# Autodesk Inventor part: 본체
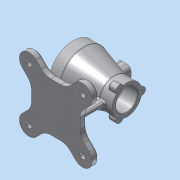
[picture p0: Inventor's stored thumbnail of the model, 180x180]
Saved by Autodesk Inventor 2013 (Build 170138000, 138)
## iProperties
Created: 2018-03
Part Number: 본체
Material: 알루미늄 6061
Document SubType Name: Modeling
Designer: Administrator
Density: 2.71 g/cm^3
Mass: 1014.37 g
Surface Area: 854.98 cm^2
Volume: 374.307 cm^3
Author: Administrator
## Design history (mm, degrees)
sketch "스케치1"
  geometry: L1 (-50, 0)-(-50, 45); L2 (50, 27.5)-(50, 0); L3 (50, 0)-(-50, 0); L4 (-70, 0)-(70, 0) reference; L5 (-50, 45)-(-30, 45); L6 (0, 54)-(0, -9) reference; L7 (-30, 45)-(27, 27.5); L8 (50, 27.5)-(27, 27.5); 1 further point
  constraints: 12 end point, 2 parallel, 2 perpendicular, 1 vertical, 1 other
  dimensions: "d0" = 90 diameter of L1.end L4; "d1" = 55 diameter of L2.start L4; "d2" = 20 distance of L1.end L5.end; "d3" = 100 distance of L2.end L1.start; "d4" = 45 distance of L1.end L1.start; "d58" = 77 distance from line of L7.end L1
revolve "회전1" sketch "스케치1" stored, may be unused: angle "d5" = 90 deg
node "작업 평면1"
sketch "스케치2"
  geometry: L1 (-0.013, 0.013)-(49.485, 49.51); L2 (-104.917, 0)-(104.917, 0) reference; L3 (0, -104.952)-(0, 104.952) reference; L4 (0, 25.481)-(36.757, 62.238); L5 (25.43, 0)-(62.213, 36.782); L6 (0, 25.481)-(-36.757, 62.238); L7 (-25.43, 0)-(-62.213, 36.782); L8 (0, -25.481)-(36.757, -62.238); L9 (0, -25.481)-(-36.757, -62.238); L10 (25.43, 0)-(62.213, -36.782); L11 (-25.43, 0)-(-62.213, -36.782); L12 (-45.013, 45.013)-(44.987, 45.013); L13 (44.987, 45.013)-(44.987, -44.987); L14 (44.987, -44.987)-(-45.013, -44.987); L15 (-45.013, -44.987)-(-45.013, 45.013); L16 (-45.013, 45.013)-(44.987, -44.987); L17 (44.987, 45.013)-(-45.013, -44.987); A1 r 70 centre (-0.013, 0.013) between (49.485, 49.51) and (35.226, 60.496); A2 r 18 centre (49.485, 49.51) between (60.471, 35.251) and (35.226, 60.496); A3 r 18 centre (-49.485, 49.51) between (-35.226, 60.496) and (-60.471, 35.251); A4 r 18 centre (49.485, -49.51) between (35.226, -60.496) and (60.471, -35.251); A5 r 18 centre (-49.485, -49.51) between (-60.471, -35.251) and (-35.226, -60.496)
  constraints: 30 end point, 19 point on circle, 17 symmetric about line, 5 centre point, 4 parallel, 2 midpoint, 2 point on line, 1 horizontal, 1 perpendicular, 4 other
  dimensions: "d11" = 140 diameter of A1; "d12" = 45 deg angle of L1 L2; "d14" = 36 diameter of A2; "d15" = 36 distance between parallel lines of L4 L5; "d16" = 25.46855 distance of L1.start L4.start; "d17" = 25.43042 distance from line of L3 L5.start; "d18" = 90 distance of L13.end L14.end; "d19" = 90 distance of L12.end L13.end
extrude "돌출1" join sketch "스케치2" distance "d20" = 12; taper "d21" = 0 deg
sketch "스케치3"
  geometry: L1 (-37, 4)-(37, 4); L2 (37, 4)-(37, -4); L3 (37, -4)-(-37, -4); L4 (-37, -4)-(-37, 4); L5 (-37, 4)-(37, -4); L6 (37, 4)-(-37, -4); 1 further point
  constraints: 12 end point, 2 midpoint, 2 parallel, 1 horizontal, 1 perpendicular
  dimensions: "d22" = 74 distance of L2.end L3.end; "d24" = 8 distance of L1.end L2.end
extrude "돌출2" join sketch "스케치3" stored distance "d25" = 12; taper "d26" = 0 deg
sketch "스케치4"
  geometry: 1 further point
sketch "스케치5"
  geometry: 1 further point
sketch "스케치6"
  geometry: L1 (-70, -24)-(-35.267, -20.961); L2 (-70, -19.582)-(-70, -36.782) reference; 1 further point
  constraints: 2 end point, 1 point on line
  dimensions: "d29" = 24 vertical distance of point (0, 0) L1.start; "d30" = 95 deg angle of L2 L1
feature "리브1" sketch "스케치6" dims "d31" = 1, "d32" = 8, "d33" = 0, "d34" = 0, "d35" = 1, "d36" = 1
node "작업 평면3"
sketch "스케치7"
  geometry: L1 (-52.5, 12.5)-(-27.5, 12.5); L2 (-27.5, 12.5)-(-27.5, -12.5); L3 (-27.5, -12.5)-(-52.5, -12.5); L4 (-52.5, -12.5)-(-52.5, 12.5); L5 (-52.5, 12.5)-(-27.5, -12.5); L6 (-27.5, 12.5)-(-52.5, -12.5); L7 (10, 45)-(10, -45) reference; L8 (-134.479, 0)-(54.479, 0) reference; L9 (-47.5, 7.5)-(-32.5, -7.5); L10 (-32.5, 7.5)-(-47.5, -7.5); 3 further points
  constraints: 16 end point, 6 midpoint, 2 parallel, 1 horizontal, 1 perpendicular, 1 point on line
  dimensions: "d37" = 50 distance from line of L7 point (-40, 0); "d38" = 25 distance of L2.end L3.end; "d39" = 25 distance of L1.end L2.end
extrude "돌출3" join sketch "스케치7" stored distance "d41" = 12; taper "d42" = 0 deg
sketch "스케치8"
  geometry: L1 (47.5, 7.5)-(32.5, 7.5); L2 (32.5, 7.5)-(32.5, -7.5); L3 (32.5, -7.5)-(47.5, -7.5); L4 (47.5, -7.5)-(47.5, 7.5); L5 (47.5, 7.5)-(32.5, -7.5); L6 (32.5, 7.5)-(47.5, -7.5); 1 further point
  constraints: 12 end point, 2 midpoint, 2 parallel, 1 horizontal, 1 perpendicular
  dimensions: "d43" = 15 distance of L3.end L2.end; "d44" = 15 distance of L3.end L1.start
extrude "돌출4" cut sketch "스케치8" distance "d45" = 30; taper "d46" = 0 deg
sketch "스케치9"
  geometry: L1 (-50, 0)-(-50, 35); L2 (-50, 35)-(-27, 35); L3 (-27, 35)-(-27, 26); L4 (-27, 26)-(20, 26); L5 (20, 26)-(20, 20); L6 (20, 20)-(50, 20); L7 (50, 20)-(50, 0); L8 (50, 0)-(-50, 0); L9 (-50, -45)-(-50, 45) reference; L10 (50, -27.5)-(50, 27.5) reference; L11 (-7.5, 45)-(7.5, 45) reference; 3 further points
  constraints: 16 end point, 5 parallel, 2 midpoint, 2 perpendicular, 2 point on line, 1 vertical
  dimensions: "d47" = 23 distance of L1.end L2.end; "d49" = 47 distance of L3.end L4.end; "d50" = 70 diameter of L2 L8; "d51" = 52 diameter of L4 L8; "d52" = 40 diameter of L6 L8; "d53" = 45 distance between parallel lines of L11 L8
revolve "회전2" sketch "스케치9" stored, may be unused: angle "d54" = 90 deg
sketch "스케치10"
  geometry: 1 further point
sketch "스케치11"
  geometry: C1 r 7 at (0, 27.5); 1 further point
  constraints: 1 centre point, 1 vertical alignment, 1 other
  dimensions: "d55" = 14 diameter of C1
extrude "돌출5" join sketch "스케치11" distance "d56" = 15; taper "d57" = 0 deg
hole "구멍1" diameter "d64" = 10; stored, may be unused: countersink angle "d68" = 90 deg, drill point angle "d70" = 118 deg; dims "d62" = 10, "d63" = 10, "d65" = 6, "d66" = 4, "d67" = 2, "d69" = 8
hole "구멍2" diameter "d73" = 10; stored, may be unused: countersink angle "d77" = 90 deg, drill point angle "d79" = 118 deg; dims "d71" = 10, "d72" = 10, "d74" = 6, "d75" = 4, "d76" = 2, "d78" = 8
sketch "스케치12" dims "d80" = 80
  geometry: C1 r 45 at (0, 0) reference; 2 further points
  constraints: 1 coincident, 1 vertical alignment, 2 other
hole "구멍3" sketch "스케치12" at (0, 40) diameter "d81" = 3.242; stored, may be unused: countersink angle "d85" = 90 deg, drill point angle "d87" = 118 deg; dims "d82" = 9, "d83" = 4, "d84" = 2, "d86" = 11
hole "구멍4" diameter "d93" = 3.242; stored, may be unused: countersink angle "d97" = 90 deg, drill point angle "d99" = 118 deg; dims "d91" = 10, "d92" = 10, "d94" = 9, "d95" = 4, "d96" = 2, "d98" = 11
fillet "모깎기1" dims "d103" = 25
fillet "모깎기2" dims "d104" = 8
fillet "모깎기3" dims "d105" = 3
fillet "모깎기4" dims "d106" = 3
fillet "모깎기5" dims "d107" = 1
fillet "모깎기6" dims "d108" = 1
chamfer "모따기1" distance "d109" = 3; stored, may be unused: second distance "d110" = 2, angle "d111" = 45 deg
chamfer "모따기2" distance "d112" = 1; stored, may be unused: second distance "d113" = 2, angle "d114" = 45 deg
fillet "모깎기7" dims "d115" = 3
fillet "모깎기8" dims "d116" = 3
fillet "모깎기9" dims "d117" = 3
fillet "모깎기10" dims "d118" = 3
node "작업 평면4"
sketch "스케치13"
  geometry: L1 (45.013, -9.227)-(45.013, 9.227) reference; 2 further points
  constraints: 1 other
  dimensions: "d120" = 35 distance of point (0, 0) point (0.013, -35); "d121" = 45 distance from line of L1 point (0.013, -35)
feature "엠보싱1" sketch "스케치13" dims "d11" = 140, "d12" = 45 deg, "d14" = 36, "d15" = 36, "d16" = 25.46855, "d17" = 25.43042, "d18" = 90, "d19" = 90, "d118" = 3, "d122" = 0.5, "d123" = 0
chamfer "모따기3" distance "d124" = 1; stored, may be unused: second distance "d125" = 2, angle "d126" = 45 deg
node "솔리드1"
mirror "대칭1"
pattern_circular "원형 패턴1" dims angle "d60" = 360 deg
mirror "대칭2"
pattern_circular "원형 패턴2" dims angle "d89" = 360 deg
pattern_circular "원형 패턴3" dims angle "d101" = 360 deg
other parameters: "d6" = -82, "d119" = 0.5
